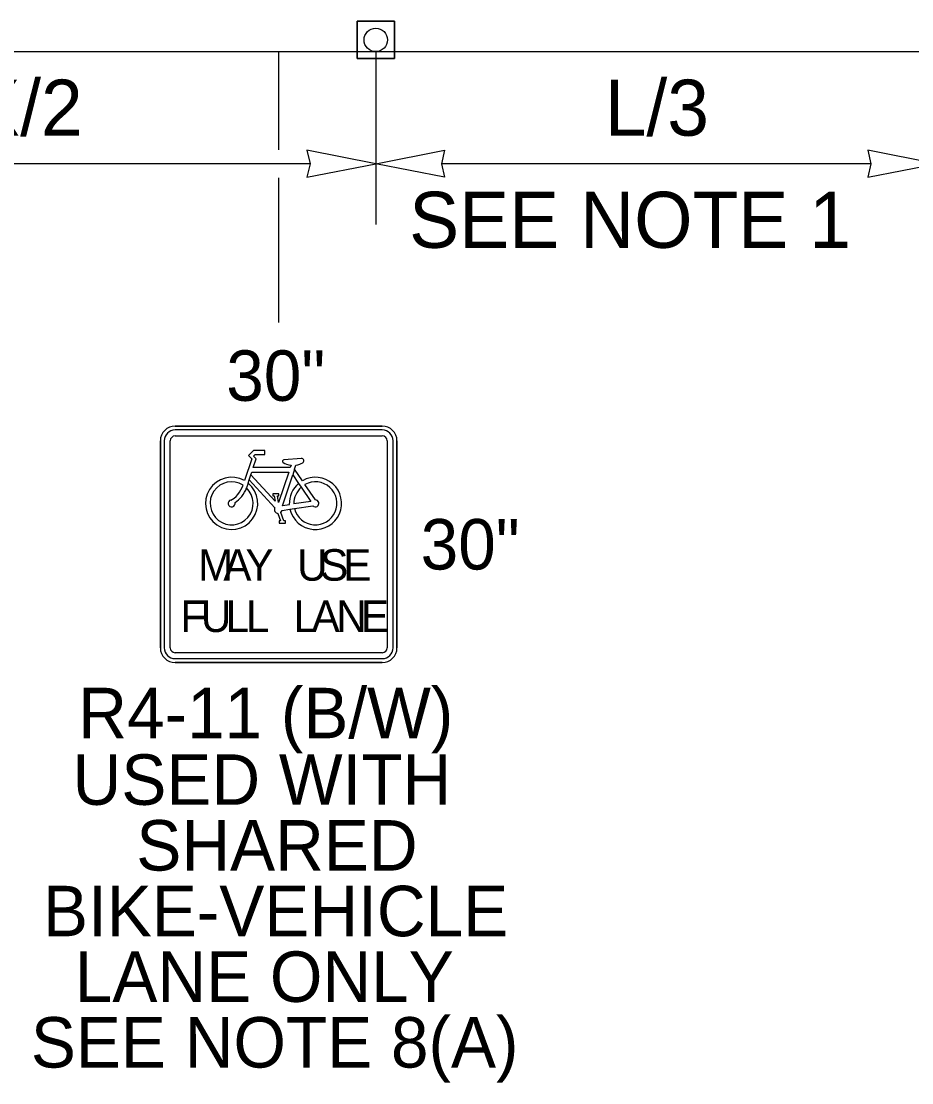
# Model space of a CAD drawing. Extents: x 99999.1 to 100096.1, y 99995 to 100010.7.
# Drawn here: x 100045.543 to 100046.813, y 100003.514 to 100005.029 of the extents above; entities that cross this region are included whole.
import ezdxf

# ---------------------------------------------------------------- set-up
doc = ezdxf.new("R2010")
doc.units = 0
for name, color, linetype in [('RD_ED_ShoulderPavedEdge', 7, 'Continuous'), ('TR_SN_ConstructionSigns', 7, 'Continuous'), ('TR_WZ_TrafficCone', 7, 'Continuous'), ('TR_WZ_WorkZoneDetails', 7, 'Continuous'), ('TR_WZ_WorkZoneTextCurrent', 7, 'Continuous')]:
    doc.layers.add(name, color=color, linetype=linetype)

msp = doc.modelspace()

# ---------------------------------------------------------------- linework, layer by layer
at = {"layer": 'RD_ED_ShoulderPavedEdge'}
msp.add_line((100040.8283, 100004.9857), (100054.8933, 100004.9857), dxfattribs=at)
at = {"layer": 'TR_SN_ConstructionSigns'}
for p, q in [((100045.7625, 100004.4514), (100046.0578, 100004.4514)), ((100046.0578, 100004.4514), (100045.7625, 100004.4514)), ((100046.0578, 100004.4514), (100045.7625, 100004.4514)), ((100046.0578, 100004.4458), (100045.7625, 100004.4458)), ((100045.7414, 100004.135), (100045.7414, 100004.4303)), ((100045.7414, 100004.4303), (100045.7414, 100004.135)), ((100045.7414, 100004.4303), (100045.7414, 100004.135)), ((100045.747, 100004.4303), (100045.747, 100004.135)), ((100045.7554, 100004.135), (100045.7554, 100004.4303)), ((100045.7625, 100004.4374), (100046.0578, 100004.4374)), ((100046.0648, 100004.4303), (100046.0648, 100004.135)), ((100046.0733, 100004.135), (100046.0733, 100004.4303)), ((100046.0789, 100004.4303), (100046.0789, 100004.135)), ((100046.0789, 100004.135), (100046.0789, 100004.4303)), ((100046.0789, 100004.135), (100046.0789, 100004.4303)), ((100045.8741, 100004.4163), (100045.8672, 100004.4093)), ((100045.8672, 100004.4093), (100045.8718, 100004.4047)), ((100045.8906, 100004.4163), (100045.8741, 100004.4163)), ((100045.8742, 100004.4086), (100045.8764, 100004.4108)), ((100045.8764, 100004.4108), (100045.8906, 100004.4108)), ((100045.8906, 100004.4108), (100045.8906, 100004.4163)), ((100045.8718, 100004.4047), (100045.8614, 100004.3735)), ((100045.874, 100004.3922), (100045.8782, 100004.4047)), ((100045.8782, 100004.4047), (100045.8742, 100004.4086)), ((100045.9425, 100004.405), (100045.9176, 100004.4034)), ((100045.9278, 100004.3955), (100045.9267, 100004.3922)), ((100045.9328, 100004.3898), (100045.9348, 100004.3957)), ((100045.8682, 100004.3746), (100045.8706, 100004.3818)), ((100045.8706, 100004.3818), (100045.8718, 100004.3856)), ((100045.9052, 100004.3441), (100045.8706, 100004.3818)), ((100045.8718, 100004.3856), (100045.9245, 100004.3856)), ((100045.9267, 100004.3922), (100045.874, 100004.3922)), ((100045.9245, 100004.3856), (100045.91, 100004.3423)), ((100045.9155, 100004.3377), (100045.9302, 100004.382)), ((100045.9328, 100004.3898), (100045.9302, 100004.382)), ((100045.9302, 100004.382), (100045.9386, 100004.3696)), ((100045.944, 100004.3734), (100045.9328, 100004.3898)), ((100045.8666, 100004.37), (100045.8644, 100004.3632)), ((100045.8666, 100004.37), (100045.8682, 100004.3746)), ((100045.8682, 100004.3746), (100045.9048, 100004.3349)), ((100045.9386, 100004.3696), (100045.9423, 100004.3641)), ((100045.9423, 100004.3641), (100045.9561, 100004.3438)), ((100045.9626, 100004.346), (100045.9477, 100004.3679)), ((100045.9105, 100004.3549), (100045.9017, 100004.3549)), ((100045.9039, 100004.3516), (100045.9052, 100004.3441)), ((100045.91, 100004.3423), (100045.9083, 100004.3516)), ((100045.9083, 100004.3516), (100045.9105, 100004.3516)), ((100045.9105, 100004.3516), (100045.9105, 100004.3549)), ((100045.9254, 100004.3392), (100045.9155, 100004.3377)), ((100045.9263, 100004.3327), (100045.9328, 100004.3337)), ((100045.9561, 100004.3438), (100045.9319, 100004.3402)), ((100045.9328, 100004.3337), (100045.9591, 100004.3376)), ((100045.9091, 100004.3268), (100045.9127, 100004.316)), ((100045.9174, 100004.316), (100045.9133, 100004.3282)), ((100045.915, 100004.331), (100045.9263, 100004.3327)), ((100045.9127, 100004.316), (100045.9109, 100004.316)), ((100045.9109, 100004.316), (100045.9109, 100004.3127)), ((100045.9109, 100004.3127), (100045.9197, 100004.3127)), ((100045.9197, 100004.316), (100045.9174, 100004.316)), ((100045.9197, 100004.3127), (100045.9197, 100004.316)), ((100046.0578, 100004.128), (100045.7625, 100004.128)), ((100045.7625, 100004.1196), (100046.0578, 100004.1196)), ((100046.0578, 100004.1139), (100045.7625, 100004.1139)), ((100045.7625, 100004.1139), (100046.0578, 100004.1139)), ((100045.7625, 100004.1139), (100046.0578, 100004.1139))]:
    msp.add_line(p, q, dxfattribs=at)
msp.add_lwpolyline([(100045.9017, 100004.3549), (100045.9017, 100004.3516), (100045.9039, 100004.3516)], dxfattribs=at)
for centre, radius, start, end in [((100045.7625, 100004.4303), 0.0211, 90, 180), ((100045.7625, 100004.4303), 0.0211, 90, 180), ((100045.7625, 100004.4303), 0.0211, 90, 180), ((100045.7625, 100004.4303), 0.0155, 90, 180), ((100046.0578, 100004.4303), 0.0211, 0, 90), ((100046.0578, 100004.4303), 0.0211, 0, 90), ((100046.0578, 100004.4303), 0.0211, 0, 90), ((100046.0578, 100004.4303), 0.0155, 0, 90), ((100045.7625, 100004.4303), 0.00703, 90, 180), ((100046.0578, 100004.4303), 0.00703, 0, 90), ((100045.9177, 100004.4012), 0.00219, 89.3854, 243.6828), ((100045.9428, 100004.4018), 0.00329, 294.5519, 96.4128), ((100045.8431, 100004.3411), 0.0373, 60.5529, 50.868), ((100045.8431, 100004.3411), 0.0307, 58.1532, 46.1649), ((100045.9626, 100004.3411), 0.0373, 130.0889, 182.8379), ((100045.9626, 100004.3411), 0.0373, 192.9622, 119.9648), ((100045.9626, 100004.3411), 0.0307, 131.3616, 181.6359), ((100045.9626, 100004.3411), 0.0307, 193.937, 119.0598), ((100045.8431, 100004.3411), 0.00493, 105.257, 14.3233), ((100045.9096, 100004.3322), 0.00548, 151.1744, 264.8566), ((100045.9626, 100004.3411), 0.00493, 225.1095, 90.4672), ((100045.9096, 100004.3322), 0.00548, 312.0053, 347.2932), ((100045.7625, 100004.135), 0.0211, 180, 270), ((100045.7625, 100004.135), 0.0211, 180, 270), ((100045.7625, 100004.135), 0.0211, 180, 270), ((100045.7625, 100004.135), 0.0155, 180, 270), ((100045.7625, 100004.135), 0.00703, 180, 270), ((100046.0578, 100004.135), 0.0211, 270, 0), ((100046.0578, 100004.135), 0.0211, 270, 0), ((100046.0578, 100004.135), 0.0155, 270, 0), ((100046.0578, 100004.135), 0.00703, 270, 0), ((100046.0578, 100004.135), 0.0211, 270, 0)]:
    msp.add_arc(centre, radius, start, end, dxfattribs=at)
for centre, major_axis, ratio, start_param, end_param in [((100045.9308, 100004.4064), (-0.0186, 0), 0.588235, 0.686048, 1.410588), ((100045.9308, 100004.4064), (-0.0186, 0), 0.588235, 1.786993, 2.401245), ((100045.848, 100004.3618), (-0.0105, -0.0158), 0.413554, 0.494612, 2.170849), ((100045.848, 100004.3618), (-0.014, -0.021), 0.55814, 0.868091, 1.989998)]:
    msp.add_ellipse(centre, major_axis=major_axis, ratio=ratio, start_param=start_param, end_param=end_param, dxfattribs=at)
at = {"layer": 'TR_WZ_TrafficCone'}
for points in [[(100046.0219, 100005.0291), (100046.0753, 100005.0291), (100046.0753, 100004.9757), (100046.0219, 100004.9757), (100046.0219, 100005.0291)], [(100046.0219, 100004.9757), (100046.0753, 100004.9757), (100046.0753, 100005.0291), (100046.0219, 100005.0291), (100046.0219, 100004.9757)]]:
    msp.add_lwpolyline(points, dxfattribs=at)
msp.add_circle((100046.0486, 100005.0024), 0.0167, dxfattribs=at)
at = {"layer": 'TR_WZ_WorkZoneDetails'}
for p, q in [((100045.9101, 100004.9857), (100045.9101, 100004.8457)), ((100046.0486, 100004.9857), (100046.0486, 100004.7391)), ((100045.9549, 100004.8257), (100045.1423, 100004.8257)), ((100046.7549, 100004.8257), (100046.1423, 100004.8257)), ((100045.9101, 100004.8057), (100045.9101, 100004.5994))]:
    msp.add_line(p, q, dxfattribs=at)
for points in [[(100046.0486, 100004.8257), (100045.9503, 100004.845), (100045.9549, 100004.8257), (100045.9503, 100004.8065)], [(100046.0486, 100004.8257), (100046.1469, 100004.845), (100046.1423, 100004.8257), (100046.1469, 100004.8065)], [(100046.8486, 100004.8257), (100046.7503, 100004.845), (100046.7549, 100004.8257), (100046.7503, 100004.8065)]]:
    msp.add_lwpolyline(points, close=True, dxfattribs=at)

# ---------------------------------------------------------------- texts
at = {"layer": 'TR_SN_ConstructionSigns'}
for s, p in [('30"', (100045.8354, 100004.4874)), ('30"', (100046.1127, 100004.2467)), ('R4-11 (B/W)', (100045.6243, 100004.0059)), ('USED WITH', (100045.6162, 100003.9109)), ('SHARED', (100045.7071, 100003.8171)), ('BIKE-VEHICLE', (100045.574, 100003.7234)), ('LANE ONLY', (100045.6194, 100003.6297)), ('SEE NOTE 8(A)', (100045.5567, 100003.536))]:
    msp.add_text(s, height=0.072, rotation=360, dxfattribs=at).set_placement(p)
for s, p in [('M', (100045.7952, 100004.2307)), ('A', (100045.8312, 100004.2307)), ('Y', (100045.8627, 100004.2307)), ('U', (100045.9365, 100004.2307)), ('S', (100045.9693, 100004.2307)), ('E', (100046.0022, 100004.2307)), ('F', (100045.77, 100004.1575)), ('U', (100045.7992, 100004.1575)), ('L', (100045.8343, 100004.1575)), ('L', (100045.8636, 100004.1575)), ('L', (100045.9315, 100004.1575)), ('A', (100045.9572, 100004.1575)), ('N', (100045.9923, 100004.1575)), ('E', (100046.0274, 100004.1575))]:
    msp.add_text(s, height=0.045, dxfattribs=at).set_placement(p)
at = {"layer": 'TR_WZ_WorkZoneTextCurrent'}
for s, p in [('X/2', (100045.4701, 100004.8657)), ('L/3', (100046.3752, 100004.8657)), ('SEE NOTE 1', (100046.0962, 100004.7057))]:
    msp.add_text(s, height=0.08, rotation=360, dxfattribs=at).set_placement(p)

doc.saveas('drawing.dxf')
